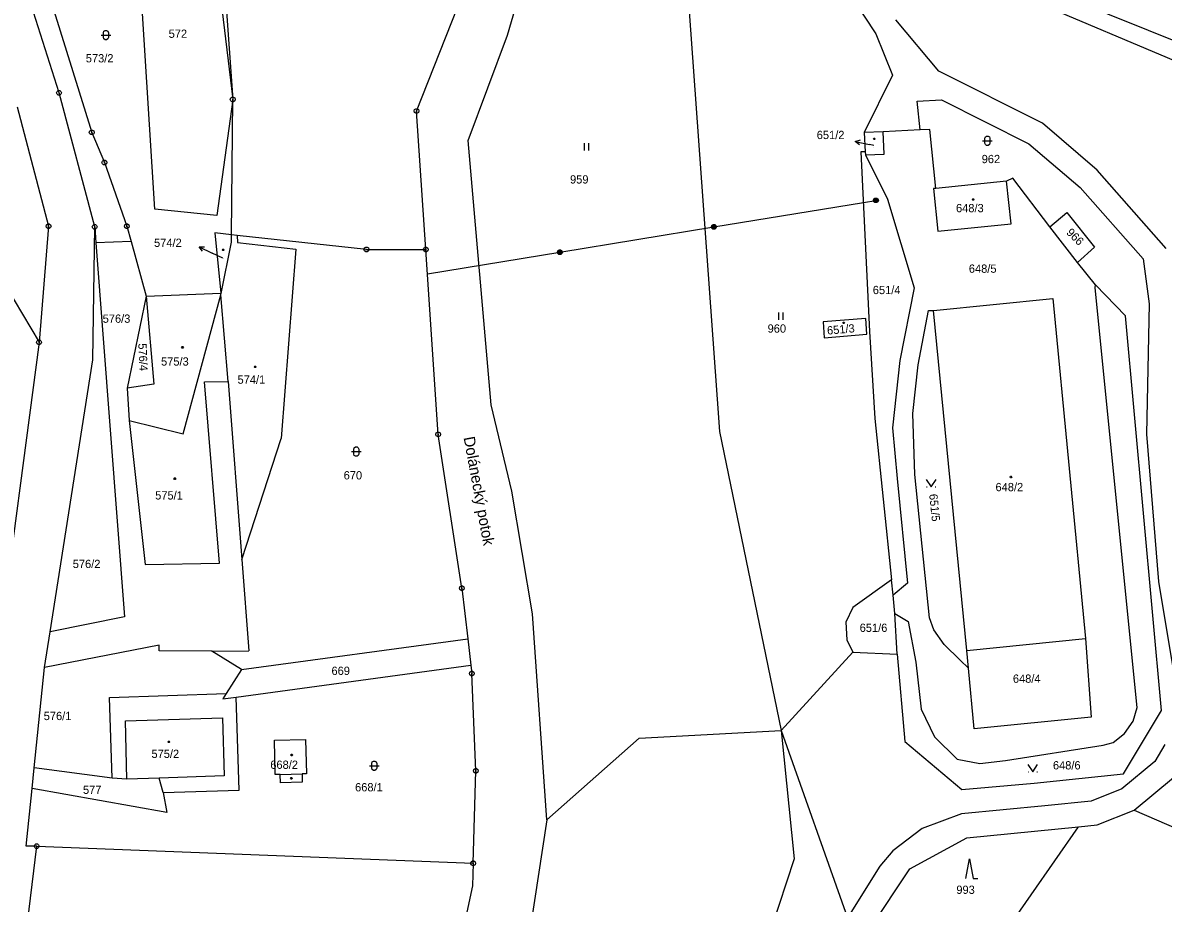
# Model space of a CAD drawing. Extents: x -812394 to -807601, y -1013098 to -1009266.
# Drawn here: x -809067 to -808832.6, y -1011988.8 to -1011807.7 of the extents above; entities that cross this region are included whole.
import ezdxf

# ---------------------------------------------------------------- set-up
doc = ezdxf.new("R2010")
doc.units = 0
for name, color, linetype in [('KN_HRANICE', 7, 'Continuous'), ('KN_KULTURY', 7, 'Continuous'), ('KN_MEZNIKY', 7, 'Continuous'), ('KN_PARCELY', 7, 'Continuous'), ('KN_SLUCKY', 7, 'Continuous'), ('KN_VEDENI', 7, 'Continuous')]:
    doc.layers.add(name, color=color, linetype=linetype)

# ---------------------------------------------------------------- blocks, each defined once
blk = doc.blocks.new('306')
for p, q in [((-0.5, 1.5), (-0.5, 0)), ((0.5, 0), (0.5, 1.5))]:
    blk.add_line(p, q)
blk = doc.blocks.new('308')
blk.add_lwpolyline([(-0.75, 0), (0, 4), (0.75, 0), (1.75, 0)])
blk = doc.blocks.new('314')
for p, q in [((-0.95, 0), (-0.85, 0)), ((0.85, 0), (0.95, 0))]:
    blk.add_line(p, q)
blk.add_lwpolyline([(-1, 1.5), (0, 0), (1, 1.5)])
blk = doc.blocks.new('316')
for points in [[(-1, 1), (0.27, 1), (1, 1)], [(-0.5, 1.5), (-0.4, 1.79), (-0.15, 1.97), (0.16, 1.97), (0.41, 1.79), (0.51, 1.5), (0.51, 0.5), (0.41, 0.21), (0.16, 0.03), (-0.15, 0.03), (-0.4, 0.21), (-0.5, 0.5), (-0.5, 1.5)]]:
    blk.add_lwpolyline(points)
blk = doc.blocks.new('NAHRADNI_SYMBOL')
blk.add_lwpolyline([(0.09, 0.15), (0.18, 0), (0.09, -0.15), (-0.09, -0.15), (-0.18, 0), (-0.09, 0.15), (0.09, 0.15)])
blk = doc.blocks.new('10292')
blk.add_line((0, 3), (0, 0))
blk.add_lwpolyline([(-0.5, 2), (0, 3), (0.5, 2)])
blk = doc.blocks.new('402')
blk.add_lwpolyline([(0.09, 0.15), (0.18, 0), (0.09, -0.15), (-0.09, -0.15), (-0.18, 0), (-0.09, 0.15), (0.09, 0.15)])
blk = doc.blocks.new('105')
blk.add_line((-0.12, 0), (0.12, 0))
blk.add_lwpolyline([(0.15, 0.48), (0.4, 0.3), (0.5, 0.01), (0.4, -0.28), (0.15, -0.46), (-0.16, -0.46), (-0.41, -0.28), (-0.51, 0.01), (-0.41, 0.3), (-0.16, 0.48), (0.15, 0.48)])
blk = doc.blocks.new('601')
blk.add_lwpolyline([(-0.15, 0.48), (0.16, 0.48), (0.41, 0.3), (0.51, 0.01), (0.41, -0.28), (0.16, -0.46), (-0.15, -0.46), (-0.4, -0.28), (-0.5, 0.01), (-0.4, 0.3), (-0.15, 0.48), (-0.12, 0.44), (0.12, 0.44), (0.28, 0.36), (-0.28, 0.36), (-0.36, 0.28), (0.36, 0.28), (0.36, 0.2), (-0.36, 0.2), (-0.4, 0.12), (0.4, 0.12), (0.44, 0.04), (-0.44, 0.04), (-0.44, -0.04), (0.44, -0.04), (0.41, -0.12), (-0.4, -0.12), (-0.39, -0.2), (0.42, -0.2), (0.37, -0.28), (-0.35, -0.28), (-0.27, -0.36), (0.29, -0.36), (0.18, -0.44), (-0.16, -0.44)])

msp = doc.modelspace()

# ---------------------------------------------------------------- linework, layer by layer
at = {"layer": 'KN_HRANICE'}
for p, q in [((-808931.65, -1011783.96), (-808923.83, -1011891.74)), ((-809059.59, -1011822.15), (-809070.64, -1011787.15)), ((-809039.91, -1011846.09), (-809043.65, -1011786.86)), ((-808904.46, -1011790.57), (-808891.7, -1011810.04)), ((-809025.76, -1011797.55), (-809023.89, -1011823.5)), ((-808863.23, -1011798.16), (-808822.56, -1011814.57)), ((-808824.78, -1011817.93), (-808865.49, -1011800.66)), ((-809026.36, -1011802.99), (-809023.89, -1011823.5)), ((-809060.63, -1011805.19), (-809052.86, -1011830.28)), ((-808986.12, -1011825.88), (-808977.69, -1011804.62)), ((-808878.74, -1011817.7), (-808887.62, -1011807.14)), ((-808891.7, -1011810.04), (-808888.3, -1011818.49)), ((-808888.3, -1011818.49), (-808894.08, -1011830.28)), ((-808857.46, -1011828.41), (-808878.74, -1011817.7)), ((-809052.26, -1011849.71), (-809059.59, -1011822.15)), ((-809023.89, -1011823.5), (-809027.18, -1011847.34)), ((-809024.13, -1011851.34), (-809023.89, -1011823.5)), ((-808882.59, -1011829.77), (-808883.19, -1011823.88)), ((-809068.2, -1011824.99), (-809061.74, -1011849.58)), ((-808984.21, -1011854.38), (-808986.12, -1011825.88)), ((-808846.2, -1011838.04), (-808857.46, -1011828.41)), ((-809052.86, -1011830.28), (-809050.26, -1011836.49)), ((-808890.2, -1011830.15), (-808894.08, -1011830.28)), ((-808894.08, -1011830.28), (-808893.88, -1011834.24)), ((-808882.59, -1011829.77), (-808890.2, -1011830.15)), ((-808893.88, -1011834.24), (-808893.84, -1011834.87)), ((-809050.26, -1011836.49), (-809045.65, -1011849.55)), ((-808832.02, -1011854.13), (-808846.2, -1011838.04)), ((-808864.84, -1011840.31), (-808879.4, -1011841.79)), ((-809027.18, -1011847.34), (-809039.91, -1011846.09)), ((-809077.97, -1011849.39), (-809063.7, -1011873.44)), ((-809061.74, -1011849.58), (-809063.7, -1011873.44)), ((-809052.63, -1011877.06), (-809052.26, -1011849.71)), ((-809052.26, -1011849.71), (-809052.01, -1011852.97)), ((-809045.65, -1011849.55), (-809044.79, -1011852.69)), ((-808850.26, -1011857.04), (-808855.95, -1011849.71)), ((-809024.13, -1011851.34), (-809027.58, -1011850.96)), ((-809027.58, -1011850.96), (-809026.36, -1011863.36)), ((-809024.14, -1011852.83), (-809024.13, -1011851.34)), ((-809022.98, -1011851.46), (-809024.13, -1011851.34)), ((-808996.4, -1011854.34), (-809022.98, -1011851.46)), ((-809022.98, -1011851.46), (-809022.88, -1011852.88)), ((-809044.79, -1011852.69), (-809052.01, -1011852.97)), ((-809052.01, -1011852.97), (-809046.12, -1011929.91)), ((-809044.79, -1011852.69), (-809041.69, -1011863.94)), ((-809026.27, -1011863.41), (-809024.14, -1011852.83)), ((-809022.88, -1011852.88), (-809010.89, -1011854.29)), ((-809010.89, -1011854.29), (-809013.96, -1011893.21)), ((-808996.4, -1011854.34), (-808984.21, -1011854.38)), ((-808981.65, -1011892.37), (-808984.21, -1011854.38)), ((-808836.77, -1011856.3), (-808835.53, -1011865.5)), ((-808846.55, -1011861.6), (-808850.26, -1011857.04)), ((-808840.38, -1011868), (-808846.55, -1011861.6)), ((-809041.69, -1011863.94), (-809045.57, -1011882.86)), ((-809041.69, -1011863.94), (-809026.36, -1011863.36)), ((-809041.69, -1011863.94), (-809040.13, -1011882.07)), ((-809034.07, -1011892.23), (-809026.34, -1011863.65)), ((-809026.34, -1011863.65), (-809026.36, -1011863.36)), ((-809026.34, -1011863.65), (-809026.27, -1011863.41)), ((-809024.85, -1011881.48), (-809026.34, -1011863.65)), ((-808835.53, -1011865.5), (-808836.1, -1011892.3)), ((-808873.02, -1011936.78), (-808879.87, -1011866.88)), ((-808833.01, -1011949.12), (-808840.38, -1011868)), ((-809063.7, -1011873.44), (-809073.39, -1011946.52)), ((-809061.41, -1011932.96), (-809052.63, -1011877.06)), ((-809040.13, -1011882.07), (-809045.57, -1011882.86)), ((-809029.72, -1011881.59), (-809024.85, -1011881.48)), ((-809026.6, -1011918.86), (-809029.72, -1011881.59)), ((-809024.85, -1011881.48), (-809022.04, -1011918.12)), ((-809045.57, -1011882.86), (-809045.15, -1011889.54)), ((-809045.15, -1011889.54), (-809034.07, -1011892.23)), ((-809045.15, -1011889.54), (-809041.91, -1011919.15)), ((-808923.83, -1011891.74), (-808911.18, -1011953.22)), ((-809022.04, -1011918.12), (-809013.96, -1011893.21)), ((-808976.79, -1011923.99), (-808981.65, -1011892.37)), ((-808836.1, -1011892.3), (-808833.61, -1011922.64)), ((-809041.91, -1011919.15), (-809026.6, -1011918.86)), ((-809022.04, -1011918.12), (-809020.6, -1011936.88)), ((-808888.16, -1011925.45), (-808888.48, -1011922.27)), ((-808976.79, -1011923.99), (-808975.57, -1011934.41)), ((-808833.61, -1011922.64), (-808829.13, -1011949.41)), ((-808887.78, -1011929.2), (-808888.16, -1011925.45)), ((-808887.35, -1011937.54), (-808887.78, -1011929.2)), ((-809046.12, -1011929.91), (-809061.41, -1011932.96)), ((-809062.56, -1011940.27), (-809061.41, -1011932.96)), ((-809038.99, -1011935.72), (-809062.56, -1011940.27)), ((-809039.01, -1011936.88), (-809038.99, -1011935.72)), ((-809022.06, -1011940.69), (-808975.57, -1011934.41)), ((-808975.57, -1011934.41), (-808974.94, -1011939.81)), ((-808873.02, -1011936.78), (-808848.59, -1011934.33)), ((-809028.15, -1011936.97), (-809039.01, -1011936.88)), ((-809028.15, -1011936.97), (-809020.6, -1011936.88)), ((-809022.06, -1011940.69), (-809028.15, -1011936.97)), ((-808896.46, -1011937.12), (-808911.18, -1011953.22)), ((-808896.46, -1011937.12), (-808887.35, -1011937.54)), ((-808887.35, -1011937.54), (-808885.73, -1011955.49)), ((-808872.67, -1011940.47), (-808873.02, -1011936.78)), ((-809064.7, -1011960.93), (-809062.56, -1011940.27)), ((-809022.06, -1011940.69), (-809025.24, -1011945.65)), ((-809023.21, -1011946.38), (-808974.94, -1011939.81)), ((-808974.94, -1011939.81), (-808974.74, -1011941.54)), ((-808871.48, -1011952.88), (-808872.67, -1011940.47)), ((-808973.92, -1011961.54), (-808974.74, -1011941.54)), ((-809049.23, -1011946.44), (-809025.24, -1011945.65)), ((-809025.24, -1011945.65), (-809025.95, -1011946.75)), ((-809048.7, -1011963.03), (-809049.23, -1011946.44)), ((-809025.95, -1011946.75), (-809023.21, -1011946.38)), ((-809022.59, -1011965.49), (-809023.21, -1011946.38)), ((-808840.81, -1011962.15), (-808833.01, -1011949.12)), ((-809015.29, -1011955.26), (-809008.9, -1011955.07)), ((-809015.14, -1011962.32), (-809015.29, -1011955.26)), ((-809008.9, -1011955.07), (-809008.74, -1011962.13)), ((-808911.18, -1011953.22), (-808897.5, -1011991.75)), ((-808911.18, -1011953.22), (-808908.48, -1011979.67)), ((-808885.73, -1011955.49), (-808874.04, -1011965.37)), ((-808832.28, -1011956.16), (-808834.38, -1011959.6)), ((-808834.38, -1011959.6), (-808841.18, -1011965.26)), ((-809065.14, -1011965.21), (-809064.7, -1011960.93)), ((-809048.7, -1011963.03), (-809064.7, -1011960.93)), ((-809014.14, -1011962.29), (-809015.14, -1011962.32)), ((-809014.09, -1011963.99), (-809014.14, -1011962.29)), ((-809008.74, -1011962.13), (-809009.64, -1011962.15)), ((-809009.64, -1011962.15), (-809009.59, -1011963.86)), ((-808974.48, -1011980.56), (-808973.92, -1011961.54)), ((-808859.18, -1011964.05), (-808840.81, -1011962.15)), ((-809045.66, -1011963.24), (-809048.7, -1011963.03)), ((-809039.01, -1011963.02), (-809045.66, -1011963.24)), ((-809038.2, -1011965.99), (-809039.01, -1011963.02)), ((-809009.59, -1011963.86), (-809014.09, -1011963.99)), ((-808874.04, -1011965.37), (-808859.18, -1011964.05)), ((-808838.58, -1011969.6), (-808830.54, -1011962.92)), ((-809066.37, -1011977.01), (-809065.14, -1011965.21)), ((-809037.44, -1011970.1), (-809065.14, -1011965.21)), ((-809038.2, -1011965.99), (-809022.59, -1011965.49)), ((-809038.2, -1011965.99), (-809037.44, -1011970.1)), ((-808841.18, -1011965.26), (-808847.43, -1011967.77)), ((-808856.99, -1011968.74), (-808874.11, -1011970.38)), ((-808847.43, -1011967.77), (-808856.99, -1011968.74)), ((-808959.35, -1011971.59), (-808963.83, -1012000.81)), ((-808874.11, -1011970.38), (-808882.18, -1011973.42)), ((-808846.23, -1011972.67), (-808838.58, -1011969.6)), ((-808838.58, -1011969.6), (-808820.74, -1011977.44)), ((-808882.18, -1011973.42), (-808888.21, -1011978.01)), ((-808872.97, -1011975.3), (-808850.04, -1011973.04)), ((-808867.42, -1011997.93), (-808850.04, -1011973.04)), ((-808850.04, -1011973.04), (-808846.23, -1011972.67)), ((-808884.75, -1011981.67), (-808872.97, -1011975.3)), ((-809064.18, -1011977.03), (-809066.37, -1011977.01)), ((-809066.1, -1011992.82), (-809064.18, -1011977.03)), ((-809064.18, -1011977.03), (-808974.48, -1011980.56)), ((-808888.21, -1011978.01), (-808890.89, -1011981.16)), ((-808908.48, -1011979.67), (-808935.3, -1012060.33)), ((-808890.89, -1011981.16), (-808897.5, -1011991.75)), ((-808892.86, -1011993.95), (-808884.75, -1011981.67))]:
    msp.add_line(p, q, dxfattribs=at)
for points in [[(-808959.35, -1011971.59), (-808962.28, -1011929.28), (-808966.55, -1011904.05), (-808970.77, -1011886.31), (-808975.49, -1011831.97), (-808967.41, -1011810.26), (-808962, -1011791.72), (-808962.72, -1011776.44), (-808967.65, -1011744.41), (-808976.79, -1011718.1), (-808983.84, -1011699.49)], [(-808883.19, -1011823.88), (-808878.19, -1011823.57), (-808860.25, -1011832.6), (-808849.72, -1011841.61), (-808836.77, -1011856.3)], [(-808893.84, -1011834.87), (-808890.02, -1011834.72), (-808890.2, -1011830.15)], [(-808879.4, -1011841.79), (-808880.63, -1011829.68), (-808882.59, -1011829.77)], [(-808893.88, -1011834.24), (-808894.76, -1011834.28), (-808893.01, -1011871.23)], [(-808893.84, -1011834.87), (-808889.29, -1011844), (-808883.81, -1011862.26), (-808886.75, -1011877.15), (-808888.29, -1011891.01), (-808887.29, -1011901.41), (-808885.17, -1011922.93), (-808888.16, -1011925.45)], [(-808879.4, -1011841.79), (-808879.88, -1011841.84), (-808878.95, -1011850.6), (-808863.92, -1011849.05), (-808864.84, -1011840.31)], [(-808855.95, -1011849.71), (-808863.54, -1011839.67), (-808864.84, -1011840.31)], [(-808855.95, -1011849.71), (-808852.45, -1011846.77), (-808846.73, -1011853.9), (-808850.26, -1011857.04)], [(-808887.78, -1011929.2), (-808885.07, -1011930.82), (-808883.5, -1011939.23), (-808882.39, -1011948.87), (-808879.68, -1011954.55), (-808874.99, -1011959.17), (-808870.31, -1011960.06), (-808865.03, -1011959.42), (-808844.96, -1011956.28), (-808842.95, -1011955.72), (-808840.61, -1011953.86), (-808838.84, -1011951.35), (-808838, -1011948.54), (-808846.62, -1011862.26), (-808846.55, -1011861.6)], [(-808879.87, -1011866.88), (-808855.34, -1011864.41), (-808848.59, -1011934.33)], [(-808872.67, -1011940.47), (-808874.38, -1011938.81), (-808877.69, -1011935.6), (-808879.76, -1011932.53), (-808880.66, -1011930.1), (-808883.68, -1011900.63), (-808884.13, -1011888.05), (-808883.02, -1011878.06), (-808880.88, -1011866.9), (-808879.87, -1011866.88)], [(-808893.01, -1011871.23), (-808891.88, -1011889.12), (-808888.48, -1011922.27)], [(-808888.48, -1011922.27), (-808896.42, -1011927.97), (-808897.88, -1011930.98), (-808897.64, -1011934.58), (-808896.46, -1011937.12)], [(-808848.59, -1011934.33), (-808847.44, -1011950.5), (-808871.48, -1011952.88)], [(-808959.35, -1011971.59), (-808940.32, -1011954.86), (-808911.18, -1011953.22)], [(-808974.48, -1011980.56), (-808974.62, -1011985.2), (-808982.73, -1012023.07), (-808996.8, -1012054.74), (-809006.95, -1012078.24), (-809012.27, -1012096.04), (-809020.39, -1012144.75)]]:
    msp.add_lwpolyline(points, dxfattribs=at)
msp.add_lwpolyline([(-808893.79, -1011868.51), (-808902.55, -1011869.21), (-808902.3, -1011872.54), (-808893.56, -1011871.77)], close=True, dxfattribs=at)
at = {"layer": 'KN_PARCELY'}
for p, q in [((-808892.14, -1011832.94), (-808893.03, -1011832.75)), ((-809025.95, -1011856.15), (-809028.1, -1011855.12))]:
    msp.add_line(p, q, dxfattribs=at)
at = {"layer": 'KN_SLUCKY'}
for p, q in [((-809045.95, -1011951.29), (-809025.99, -1011950.66)), ((-809025.99, -1011950.66), (-809025.67, -1011962.57)), ((-809045.66, -1011963.24), (-809045.95, -1011951.29)), ((-809014.14, -1011962.29), (-809009.64, -1011962.15)), ((-809025.67, -1011962.57), (-809039.01, -1011963.02))]:
    msp.add_line(p, q, dxfattribs=at)
at = {"layer": 'KN_VEDENI'}
for p, q in [((-808924.99, -1011849.72), (-808894.27, -1011844.67)), ((-808894.27, -1011844.67), (-808891.7, -1011844.25)), ((-808956.65, -1011854.92), (-808924.99, -1011849.72)), ((-808983.87, -1011859.39), (-808956.65, -1011854.92))]:
    msp.add_line(p, q, dxfattribs=at)

# ---------------------------------------------------------------- block references
at = {"layer": 'KN_KULTURY'}
for name, p in [('316', (-809049.96, -1011811.27)), ('316', (-808868.78, -1011832.99)), ('306', (-808951.18, -1011833.99)), ('402', (-808892.04, -1011831.59)), ('402', (-808871.71, -1011844.06)), ('NAHRADNI_SYMBOL', (-809025.85, -1011854.43)), ('306', (-808911.24, -1011868.78)), ('402', (-808898.34, -1011869.41)), ('NAHRADNI_SYMBOL', (-809034.22, -1011874.46)), ('NAHRADNI_SYMBOL', (-809019.27, -1011878.47)), ('316', (-808998.5, -1011896.91)), ('402', (-809035.79, -1011901.47)), ('402', (-808863.95, -1011901.12)), ('314', (-808880.33, -1011903.12)), ('402', (-809037.02, -1011955.58)), ('402', (-809011.79, -1011958.29)), ('316', (-808994.81, -1011961.51)), ('314', (-808859.45, -1011961.74)), ('402', (-809011.82, -1011963.1)), ('308', (-808872.46, -1011983.65))]:
    msp.add_blockref(name, p, dxfattribs=at)
at = {"layer": 'KN_MEZNIKY'}
for p in [(-809059.59, -1011822.15), (-809023.89, -1011823.5), (-808986.12, -1011825.88), (-809052.86, -1011830.28), (-809050.26, -1011836.49), (-809061.74, -1011849.58), (-809052.26, -1011849.71), (-809045.65, -1011849.55), (-808996.4, -1011854.34), (-808984.21, -1011854.38), (-809063.7, -1011873.44), (-808981.65, -1011892.37), (-808976.79, -1011923.99), (-808974.74, -1011941.54), (-808973.92, -1011961.54), (-809064.18, -1011977.03), (-808974.48, -1011980.56)]:
    msp.add_blockref('105', p, dxfattribs=at)
at = {"layer": 'KN_PARCELY'}
for p, rotation in [((-808893.03, -1011832.75), 77.750373), ((-809028.1, -1011855.12), 64.400456)]:
    msp.add_blockref('10292', p, dxfattribs=dict(at, rotation=rotation))
at = {"layer": 'KN_VEDENI'}
for p in [(-808891.7, -1011844.25), (-808924.99, -1011849.72), (-808956.65, -1011854.92)]:
    msp.add_blockref('601', p, dxfattribs=at)

# ---------------------------------------------------------------- texts
at = {"layer": 'KN_PARCELY'}
for s, height, p in [('572', 1.7, (-809037.06, -1011810.83)), ('573/2', 1.7, (-809054.09, -1011815.88)), ('651/2', 1.7, (-808903.85, -1011831.65)), ('651/2', 0.1, (-808892.27, -1011833.38)), ('962', 1.7, (-808869.95, -1011836.6)), ('959', 1.7, (-808954.56, -1011840.79)), ('648/3', 1.7, (-808875.23, -1011846.69)), ('574/2', 1.7, (-809040.06, -1011853.82)), ('648/5', 1.7, (-808872.59, -1011859.14)), ('651/4', 1.7, (-808892.33, -1011863.53)), ('576/3', 1.7, (-809050.62, -1011869.42)), ('960', 1.7, (-808913.95, -1011871.45)), ('575/3', 1.7, (-809038.62, -1011878.23)), ('574/1', 1.7, (-809022.9, -1011881.95)), ('670', 1.7, (-809001.09, -1011901.63)), ('648/2', 1.7, (-808867.11, -1011904.05)), ('575/1', 1.7, (-809039.83, -1011905.76)), ('576/2', 1.7, (-809056.77, -1011919.85)), ('651/6', 1.7, (-808895.03, -1011932.98)), ('669', 1.7, (-809003.59, -1011941.83)), ('648/4', 1.7, (-808863.54, -1011943.44)), ('576/1', 1.7, (-809062.74, -1011951.11)), ('575/2', 1.7, (-809040.59, -1011958.9)), ('668/2', 1.7, (-809016.17, -1011961.14)), ('648/6', 1.7, (-808855.31, -1011961.26)), ('577', 1.7, (-809054.67, -1011966.29)), ('668/1', 1.7, (-808998.74, -1011965.77)), ('993', 1.7, (-808875.16, -1011986.85))]:
    msp.add_text(s, height=height, dxfattribs=at).set_placement(p)
for s, height, rotation, p in [('966', 1.7, 315.471, (-808852.68, -1011851.01)), ('574/2', 0.1, 357.182, (-809025.97, -1011856.18)), ('651/3', 1.7, 5.099, (-808901.66, -1011871.87)), ('576/4', 1.7, 272.785, (-809043.31, -1011873.68)), ('Dolánecký potok', 2.3, 280.463, (-808976.45, -1011893.02)), ('651/5', 1.7, 275.936, (-808880.75, -1011904.69))]:
    msp.add_text(s, height=height, rotation=rotation, dxfattribs=at).set_placement(p)

doc.saveas('drawing.dxf')
